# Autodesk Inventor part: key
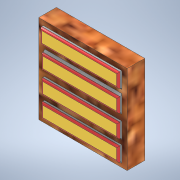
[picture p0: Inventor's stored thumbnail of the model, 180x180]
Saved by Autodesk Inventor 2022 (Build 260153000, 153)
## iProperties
Created: 2021-06
Part Number: key
Material: Generic
Document SubType Name: Modeling
Designer: Dell
Density: 1 g/cm^3
Appearance: Default
Author: Dell
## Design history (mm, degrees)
sketch "Sketch1"
  geometry: L1 (-12.5, 12.5)-(12.5, 12.5); L2 (12.5, 12.5)-(12.5, -12.5); L3 (12.5, -12.5)-(-12.5, -12.5); L4 (-12.5, -12.5)-(-12.5, 12.5); L5 (-12.5, 12.5)-(12.5, -12.5); L6 (12.5, 12.5)-(-12.5, -12.5); 1 further point
  constraints: 12 end point, 2 midpoint, 2 parallel, 1 horizontal, 1 perpendicular
  dimensions: "d0" = 25 distance of L2.end L3.end; "d1" = 25 distance of L1.end L2.end
extrude "Extrusion1" new body sketch "Sketch1" distance "d2" = 5; taper "d3" = 0 deg
sketch "Sketch2"
  geometry: L1 (-11.16, 11.203)-(10.985, 11.203); L2 (10.985, 11.203)-(10.985, 7.141); L3 (10.985, 7.141)-(-11.16, 7.141); L4 (-11.16, 7.141)-(-11.16, 11.203); L5 (-10.854, 5.132)-(10.985, 5.132); L6 (10.985, 5.132)-(10.985, 1.07); L7 (10.985, 1.07)-(-10.854, 1.07); L8 (-10.854, 1.07)-(-10.854, 5.132); L9 (-10.854, -1.114)-(10.985, -1.114); L10 (10.985, -1.114)-(10.985, -5.132); L11 (10.985, -5.132)-(-10.854, -5.132); L12 (-10.854, -5.132)-(-10.854, -1.114); L13 (-10.854, -6.923)-(10.985, -6.923); L14 (10.985, -6.923)-(10.985, -10.941); L15 (10.985, -10.941)-(-10.854, -10.941); L16 (-10.854, -10.941)-(-10.854, -6.923); 1 further point
  constraints: 32 end point, 8 parallel, 4 horizontal, 4 perpendicular, 2 point on line
extrude "Extrusion2" join sketch "Sketch2" distance "d4" = 1; taper "d5" = 0 deg
fillet "Fillet1" dims "d6" = 0.5
fillet "Fillet2" dims "d7" = 0.5
body "Solid1"
